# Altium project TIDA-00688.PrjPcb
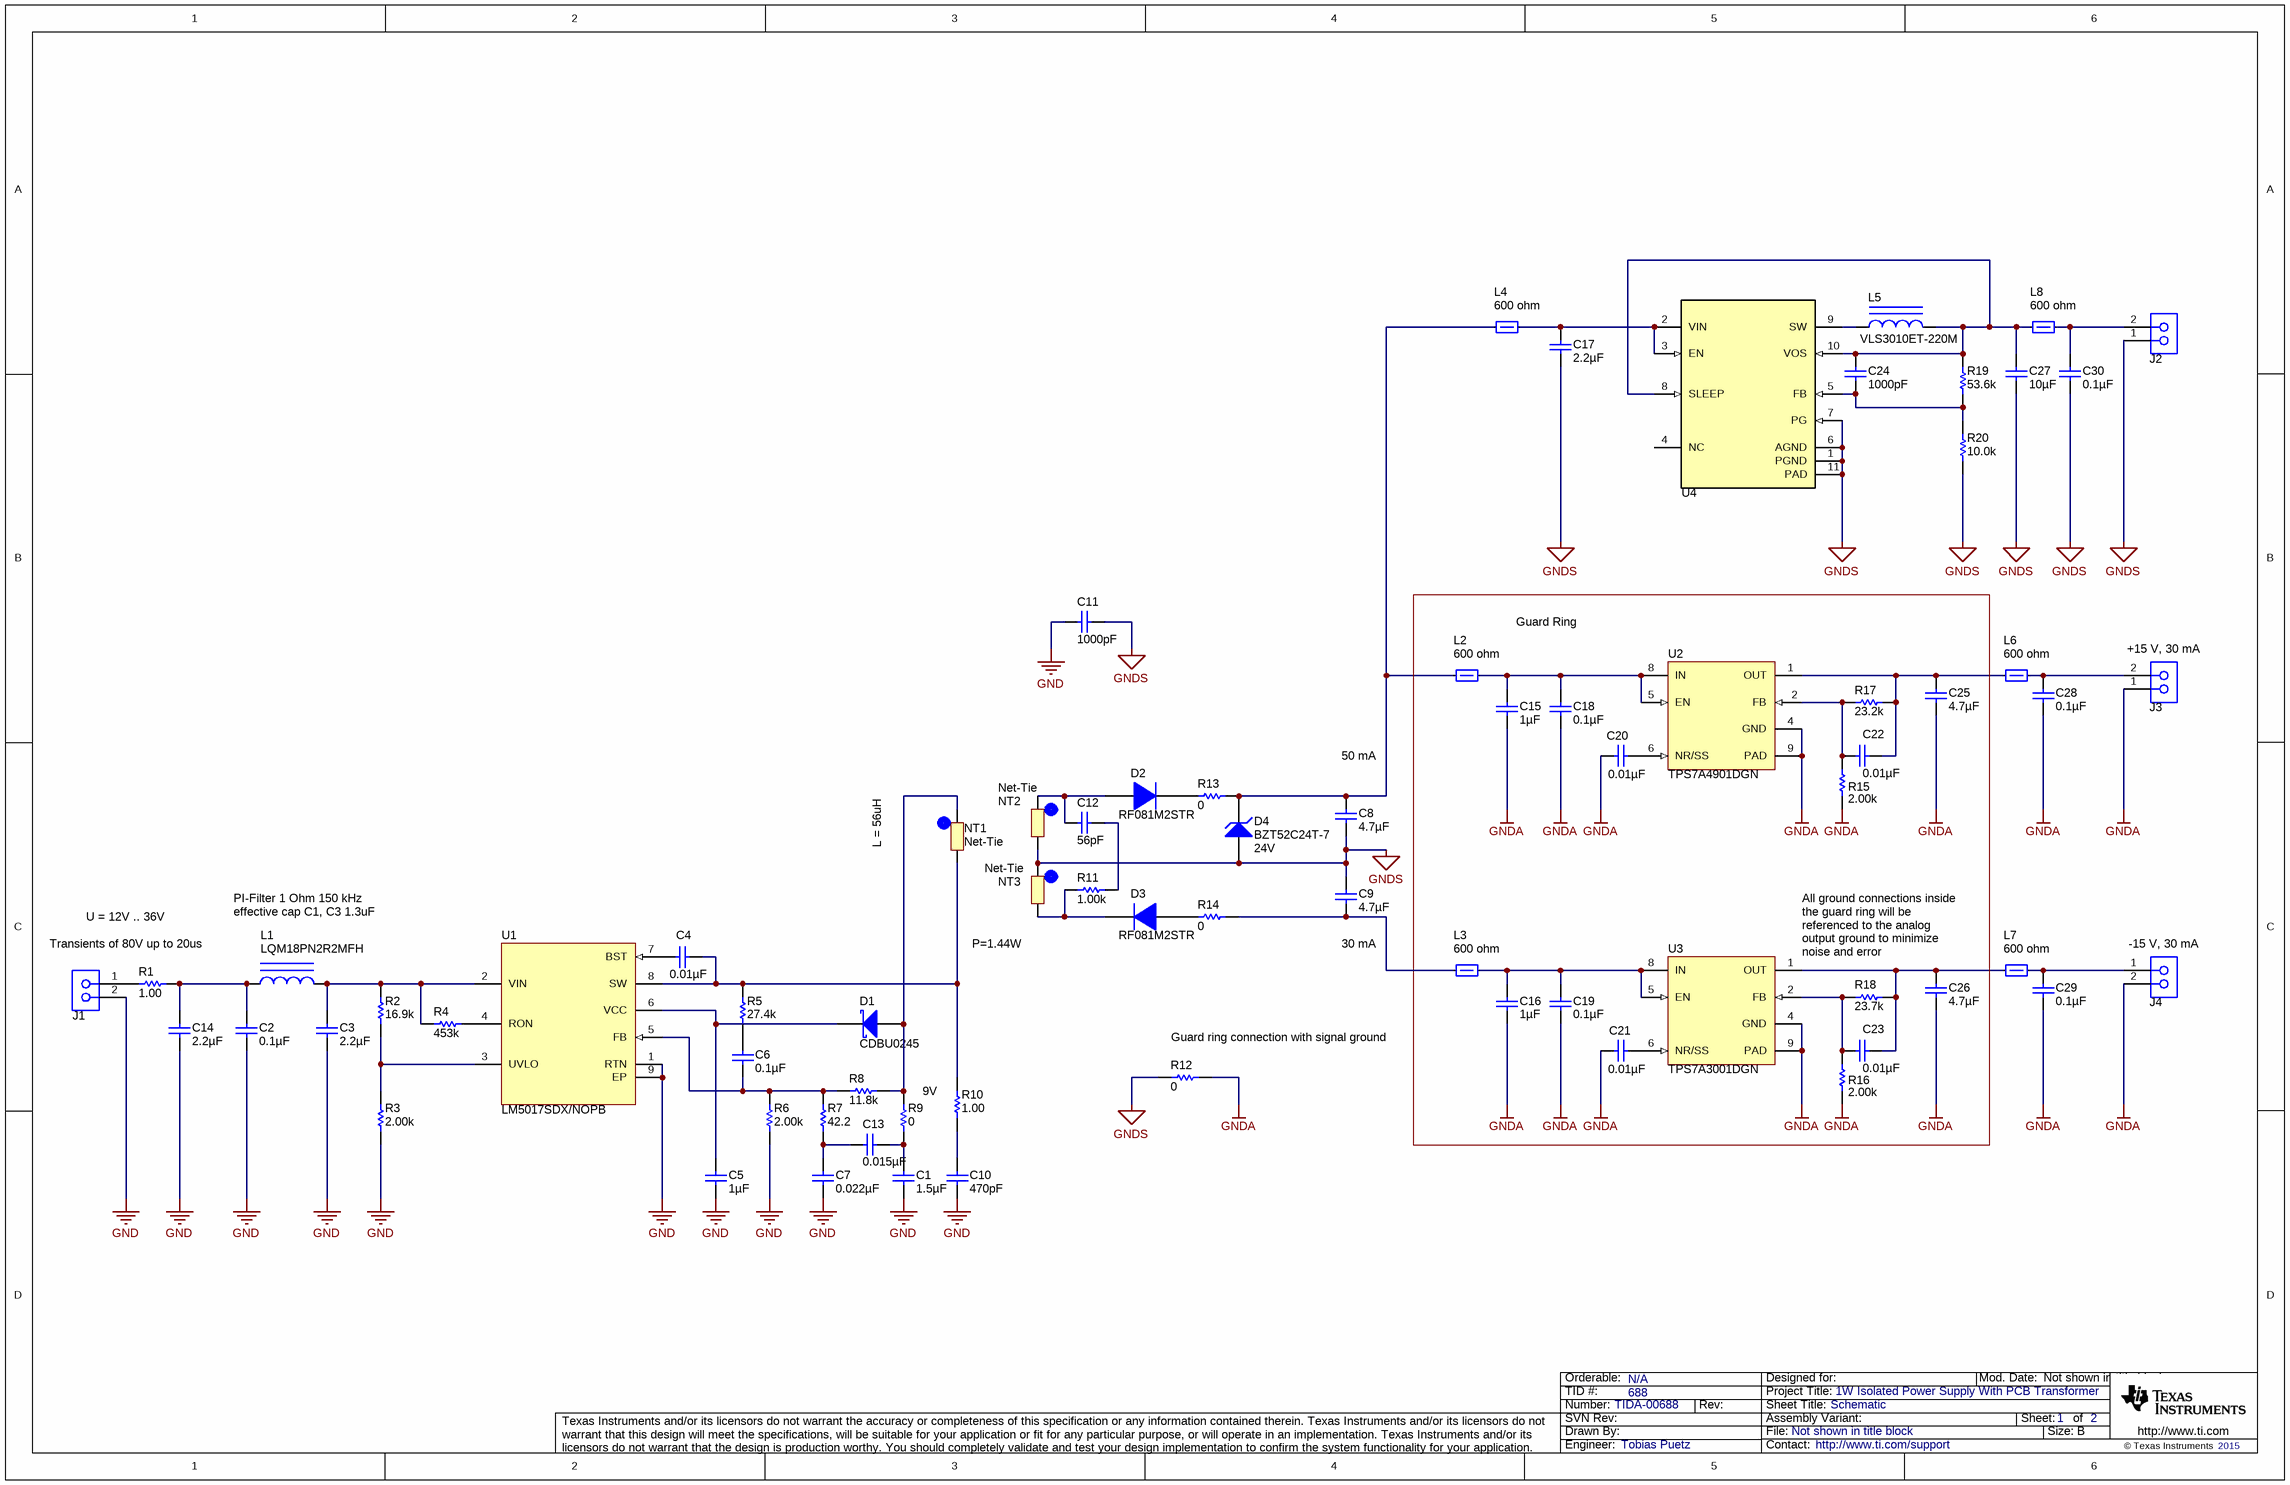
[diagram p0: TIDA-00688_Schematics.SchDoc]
CopyrightYear: 2015; EVM_Orderable: N/A; PCB_Layout: a0406826; PRJ_Engineer: Tobias Puetz; PRJ_Number: TIDA-00688; PRJ_Title: 1W Isolated Power Supply With PCB Transformer; TechSupport: http://www.ti.com/support; TID: 688
2 sheets, 83 parts. Net scope: global (net labels, ports and power ports of the same name join across sheets).
Board file: TIDA-00688.PcbDoc
Sheets:
  TIDA-00688_Schematics.SchDoc
  TIDA-00688_Hardware.SchDoc

## Sheet TIDA-00688_Schematics.SchDoc: Schematic
size 431 x 279 mm; Date: Not shown in title block; ApprovedBy: Not shown in title block; CheckedBy: Not shown in title block; Author: Not shown in title block; CompanyName: Not shown in title block; Engineer: Not shown in title block; Organization: Not shown in title block; Address1: Not shown in title block; Address2: Not shown in title block; Address3: Not shown in title block; Address4: Not shown in title block; DocumentNumber: 1; Revision: Use project parameter SCH_Rev; SheetNumber: 1; SheetTotal: 2; PageSetup: Record=PageOptions¦CenterHorizontal=True¦CenterVertical=True¦PrintScale=0.64¦XCorrection=1.00¦YCorrection=1.00¦PrintKind=0¦BorderSize=5000000¦LeftOffset=0¦BottomOffset=0¦Orientation=2¦PaperLength=1000¦PaperWidth=1000¦Scale=100¦PaperSource=15¦PrintQuality=600¦MediaType=1¦DitherType=10¦PrintScaleMode=1¦PaperKind=Letter

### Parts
C1  ValueDisplayed: 1.5µF  [0805_HV]  (hidden comment: GRM21BR71E155KA88L)
C2  ValueDisplayed: 0.1µF  [0603]  (hidden comment: C1608X7R1H104K)
C3  ValueDisplayed: 2.2µF  [1206_033]  (hidden comment: UMK316B7225KD-T)
C4  ValueDisplayed: 0.01µF  [0603]  (hidden comment: C0603C103J5RACTU)
C5  ValueDisplayed: 1µF  [0603]  (hidden comment: GRM188R71E105KA12D)
C6  ValueDisplayed: 0.1µF  [0603]  (hidden comment: GCM188R71H104KA57D)
C7  ValueDisplayed: 0.022µF  [0603]  (hidden comment: GRM188R71H223KA01D)
C8  ValueDisplayed: 4.7µF  [1206]  (hidden comment: GRM31CR71E475KA88L)
C9  ValueDisplayed: 4.7µF  [1206]  (hidden comment: GRM31CR71E475KA88L)
C10  ValueDisplayed: 470pF  [0603]  (hidden comment: C0603C471K5RACTU)
C11  ValueDisplayed: 1000pF  [1206_190]  (hidden comment: 202R18W102KV4E)
C12  ValueDisplayed: 56pF  [0805_HV]  (hidden comment: GRM21A5C2E560JW01D)
C13  ValueDisplayed: 0.015µF  [0603]  (hidden comment: GRM188R71H153KA01D)
C14  ValueDisplayed: 2.2µF  [1206_033]  (hidden comment: UMK316B7225KD-T)
C15  ValueDisplayed: 1µF  [0603]  (hidden comment: C0603C105K3RACTU)
C16  ValueDisplayed: 1µF  [0603]  (hidden comment: C0603C105K3RACTU)
C17  ValueDisplayed: 2.2µF  [0805_HV_033]  (hidden comment: C2012X7R1V225K085AC)
C18  ValueDisplayed: 0.1µF  [0603]  (hidden comment: C1608X7R1H104K)
C19  ValueDisplayed: 0.1µF  [0603]  (hidden comment: C1608X7R1H104K)
C20  ValueDisplayed: 0.01µF  [0603]  (hidden comment: C0603C103J5RACTU)
C21  ValueDisplayed: 0.01µF  [0603]  (hidden comment: C0603C103J5RACTU)
C22  ValueDisplayed: 0.01µF  [0603]  (hidden comment: C0603C103J5RACTU)
C23  ValueDisplayed: 0.01µF  [0603]  (hidden comment: C0603C103J5RACTU)
C24  ValueDisplayed: 1000pF  [0603]  (hidden comment: GRM188R71E102KA01D)
C25  ValueDisplayed: 4.7µF  [1206_033]  (hidden comment: C3216X7R1E475K085AB)
C26  ValueDisplayed: 4.7µF  [1206_033]  (hidden comment: C3216X7R1E475K085AB)
C27  ValueDisplayed: 10µF  [1206_033]  (hidden comment: C3216X7R1A106M085AC)
C28  ValueDisplayed: 0.1µF  [0603]  (hidden comment: C1608X7R1H104K)
C29  ValueDisplayed: 0.1µF  [0603]  (hidden comment: C1608X7R1H104K)
C30  ValueDisplayed: 0.1µF  [0603]  (hidden comment: C1608X7R1H104K)
D1  CDBU0245  [SOD-523F]
D2  RF081M2STR  [SOD-123]
D3  RF081M2STR  [SOD-123]
D4  BZT52C24T-7  value 24V  [SOD-523]
J1  1751248  [CONN_1751248]  (value not drawn)
J2  1751248  [CONN_1751248]  (value not drawn)
J3  1751248  [CONN_1751248]  (value not drawn)
J4  1751248  [CONN_1751248]  (value not drawn)
L1  LQM18PN2R2MFH  [0603]
L2  value 600 ohm  [0603]  (hidden comment: BLM18KG601SN1D)
L3  value 600 ohm  [0603]  (hidden comment: BLM18KG601SN1D)
L4  value 600 ohm  [0603]  (hidden comment: BLM18KG601SN1D)
L5  VLS3010ET-220M  [VLS3010]
L6  value 600 ohm  [0603]  (hidden comment: BLM18KG601SN1D)
L7  value 600 ohm  [0603]  (hidden comment: BLM18KG601SN1D)
L8  value 600 ohm  [0603]  (hidden comment: BLM18KG601SN1D)
NT1  Net-Tie  [Net-Tie_20milWide_60milLong]  (net tie, no BOM)
NT2  Net-Tie  [Net-Tie_20milWide_60milLong]  (net tie, no BOM)
NT3  Net-Tie  [Net-Tie_20milWide_60milLong]  (net tie, no BOM)
R1  ValueDisplayed: 1.00  [0603]  (hidden comment: CRCW06031R00FKEA)
R2  ValueDisplayed: 16.9k  [0603]  (hidden comment: CRCW060316K9FKEA)
R3  ValueDisplayed: 2.00k  [0603]  (hidden comment: CRCW06032K00FKEA)
R4  ValueDisplayed: 453k  [0603]  (hidden comment: CRCW0603453KFKEA)
R5  ValueDisplayed: 27.4k  [0603]  (hidden comment: CRCW060327K4FKEA)
R6  ValueDisplayed: 2.00k  [0603]  (hidden comment: CRCW06032K00FKEA)
R7  ValueDisplayed: 42.2  [0603]  (hidden comment: CRCW060342R2FKEA)
R8  ValueDisplayed: 11.8k  [0603]  (hidden comment: CRCW060311K8FKEA)
R9  ValueDisplayed: 0  [0603]  (hidden comment: ERJ-3GEY0R00V)
R10  ValueDisplayed: 1.00  [0603]  (hidden comment: CRCW06031R00FKEA)
R11  ValueDisplayed: 1.00k  [0805_HV]  (hidden comment: CRCW08051K00FKEA)
R12  ValueDisplayed: 0  [0603]  (hidden comment: CRCW06030000Z0EA)
R13  ValueDisplayed: 0  [0603]  (hidden comment: ERJ-3GEY0R00V)
R14  ValueDisplayed: 0  [0603]  (hidden comment: ERJ-3GEY0R00V)
R15  ValueDisplayed: 2.00k  [0603]  (hidden comment: CRCW06032K00FKEA)
R16  ValueDisplayed: 2.00k  [0603]  (hidden comment: CRCW06032K00FKEA)
R17  ValueDisplayed: 23.2k  [0603]  (hidden comment: CRCW060323K2FKEA)
R18  ValueDisplayed: 23.7k  [0603]  (hidden comment: CRCW060323K7FKEA)
R19  ValueDisplayed: 53.6k  [0603]  (hidden comment: CRCW060353K6FKEA)
R20  ValueDisplayed: 10.0k  [0603]  (hidden comment: CRCW060310K0FKEA)
U1  LM5017SDX/NOPB  [NGU0008B]
U2  TPS7A4901DGN  [DGN0008D_N]
U3  TPS7A3001DGN  [DGN0008D_N]
U4  TPS62175DQCR  [DQC0010A]  (value not drawn)

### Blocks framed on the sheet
Guard Ring: C15 C16 C18-C23 C25 C26 L2 L3 R15-R18 U2 U3

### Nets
GND: C1.2 C2.2 C3.2 C5.2 C7.2 C10.2 C11.2 C14.2 J1.2 R3.1 R6.1 U1.1(RTN) U1.9(EP)
GNDA: C15.2 C16.2 C18.2 C19.2 C20.1 C21.1 C25.2 C26.2 C28.2 C29.2 J3.1 J4.2 R12.2 R15.1 R16.1 U2.4(GND) U2.9(PAD) U3.4(GND) U3.9(PAD)
GNDS: C8.2 C9.1 C11.1 C17.2 C27.2 C30.2 D4.2(A) J2.1 NT2.1 NT3.1 R12.1 R20.1 U4.1(PGND) U4.6(AGND) U4.7(PG) U4.11(PAD)
NetC1_1: C1.1 C13.1 R9.1
NetC2_1: C2.1 C14.1 L1.1 R1.1
NetC3_1: C3.1 L1.2 R2.2 R4.1 U1.2(VIN)
NetC4_1: C4.1 U1.7(BST)
NetC4_2: C4.2 NT1.1 R5.1 R10.2 U1.8(SW)
NetC5_1: C5.1 D1.1(K) U1.6(VCC)
NetC6_1: C6.1 R5.2
NetC6_2: C6.2 R6.2 R7.2 R8.1 U1.5(FB)
NetC7_1: C7.1 C13.2 R7.1
NetC8_1: C8.1 D4.1(K) L2.1 L4.1 R13.1
NetC9_2: C9.2 L3.1 R14.1
NetC10_1: C10.1 R10.1
NetC12_1: C12.1 R11.1
NetC12_2: C12.2 D2.2(A) NT2.2
NetC15_1: C15.1 C18.1 L2.2 U2.5(EN) U2.8(IN)
NetC16_1: C16.1 C19.1 L3.2 U3.5(EN) U3.8(IN)
NetC17_1: C17.1 L4.2 U4.2(VIN) U4.3(EN)
NetC20_2: C20.2 U2.6(NR/SS)
NetC21_2: C21.2 U3.6(NR/SS)
NetC22_1: C22.1 R15.2 R17.1 U2.2(FB)
NetC22_2: C22.2 C25.1 L6.1 R17.2 U2.1(OUT)
NetC23_1: C23.1 R16.2 R18.1 U3.2(FB)
NetC23_2: C23.2 C26.1 L7.1 R18.2 U3.1(OUT)
NetC24_1: C24.1 C27.1 L5.2 L8.1 R19.2 U4.8(SLEEP) U4.10(VOS)
NetC24_2: C24.2 R19.1 R20.2 U4.5(FB)
NetC28_1: C28.1 J3.2 L6.2
NetC29_1: C29.1 J4.1 L7.2
NetC30_1: C30.1 J2.2 L8.2
NetD1_2: D1.2(A) NT1.2 R8.2 R9.2
NetD2_1: D2.1(K) R13.2
NetD3_1: D3.1(K) NT3.2 R11.2
NetD3_2: D3.2(A) R14.2
NetJ1_1: J1.1 R1.2
NetL5_1: L5.1 U4.9(SW)
NetR2_1: R2.1 R3.2 U1.3(UVLO)
NetR4_2: R4.2 U1.4(RON)

Not connected (* = marked no-connect by the designer): U2 3(NC) 7(DNC); U3 3(NC) 7(DNC); U4 4(NC)

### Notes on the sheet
- (near J3) +15 V, 30 mA
- (near C8) 50 mA
- L = 56uH
- U = 12V .. 36V
- Transients of 80V up to 20us
- PI-Filter 1 Ohm 150 kHz
  effective cap C1, C3 1.3uF
- (near NT3) P=1.44W
- (near C9) 30 mA
- All ground connections inside the guard ring will be referenced to the analog output ground to minimize noise and error
- (near J4) -15 V, 30 mA
- (near R12) Guard ring connection with signal ground
- 9V

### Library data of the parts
C1 = GRM21BR71E155KA88L: CAP, CERM, 1.5 µF, 25 V, +/- 10%, X7R, 0805; Manufacturer: MuRata; Polarized: N; CompType: Capacitor; Value: 1.5uF; U/M: EA; Cap_F: 0.0000015; Tolerance_%: 10; Value1: Unknown; VDC_V: 25; Value2: 25V; TaMin_C: -55; TaMax_C: 125; Cap_Case: 0805
C2 C18 C19 C28-C30 = C1608X7R1H104K: CAP, CERM, 0.1 µF, 50 V, +/- 10%, X7R, 0603; Manufacturer: TDK; Polarized: N; CompType: Capacitor; Value: 0.1uF; U/M: EA; Cap_F: 0.0000001; Tolerance_%: 10; ESR_ohm: 0.017; Value1: 0.017 ohm; VDC_V: 50; Value2: 50V; TaMin_C: -55; TaMax_C: 125
C3 C14 = UMK316B7225KD-T: CAP, CERM, 2.2 µF, 50 V, +/- 10%, X7R, 1206; Manufacturer: Taiyo Yuden; Polarized: N; CompType: Capacitor; Value: 2.2uF; U/M: EA; Cap_F: 0.0000022; Tolerance_%: 10; Value1: Unknown; VDC_V: 50; Value2: 50V; TaMin_C: -55; TaMax_C: 125; Cap_Case: 1206
C4 C20-C23 = C0603C103J5RACTU: CAP, CERM, 0.01 µF, 50 V, +/- 5%, X7R, 0603; Manufacturer: Kemet; Polarized: N; CompType: Capacitor; Value: 0.01uF; U/M: EA; Cap_F: 0.00000001; Tolerance_%: 5; Value1: Unknown; VDC_V: 50; Value2: 50V; TaMin_C: -55; TaMax_C: 125
C5 = GRM188R71E105KA12D: CAP, CERM, 1 µF, 25 V, +/- 10%, X7R, 0603; Manufacturer: MuRata; Polarized: N; CompType: Capacitor; Value: 1uF; U/M: EA; Cap_F: 0.000001; Tolerance_%: 10; Value1: Unknown; VDC_V: 25; Value2: 25V; TaMin_C: -55; TaMax_C: 125
C6 = GCM188R71H104KA57D: CAP, CERM, 0.1 µF, 50 V, +/- 10%, X7R, 0603; Manufacturer: MuRata; Polarized: N; CompType: Capacitor; Value: 0.1uF; U/M: EA; Cap_F: 0.0000001; Tolerance_%: 10; ESR_ohm: 0.02; Value1: 0.02 ohm; VDC_V: 50; Value2: 50V; IRMS_A: 1.84; TaMin_C: -55; TaMax_C: 125
C7 = GRM188R71H223KA01D: CAP, CERM, 0.022 µF, 50 V, +/- 10%, X7R, 0603; Manufacturer: MuRata; Polarized: N; CompType: Capacitor; Value: 0.022uF; U/M: EA; Cap_F: 0.000000022; Tolerance_%: 10; Value1: Unknown; VDC_V: 50; Value2: 50V; TaMin_C: -55; TaMax_C: 125; AEC Category: Q200
C8 C9 = GRM31CR71E475KA88L: CAP, CERM, 4.7 µF, 25 V, +/- 10%, X7R, 1206; Manufacturer: MuRata; Polarized: N; CompType: Capacitor; Value: 4.7uF; U/M: EA; Cap_F: 0.0000047; Tolerance_%: 10; Value1: Unknown; VDC_V: 25; Value2: 25V; TaMin_C: -55; TaMax_C: 125
C10 = C0603C471K5RACTU: CAP, CERM, 470 pF, 50 V, +/- 10%, X7R, 0603; Manufacturer: Kemet; Polarized: N; CompType: Capacitor; Value: 470pF; U/M: EA; Cap_F: 0.00000000047; Tolerance_%: 10; Value1: Unknown; VDC_V: 50; Value2: 50V; TaMin_C: -55; TaMax_C: 125
C11 = 202R18W102KV4E: CAP, CERM, 1000 pF, 2000 V, +/- 10%, X7R, 1206_190; Manufacturer: Johanson Technology; Polarized: N; CompType: Capacitor; Value: 1000pF; U/M: EA; Cap_F: 0.000000001; Tolerance_%: 10; Value1: Unknown; VDC_V: 2000; Value2: 2000V; TaMin_C: -55; TaMax_C: 125; Cap_Case: 1206
C12 = GRM21A5C2E560JW01D: CAP, CERM, 56 pF, 250 V, +/- 5%, C0G/NP0, 0805; Manufacturer: MuRata; Polarized: N; CompType: Capacitor; Value: 56pF; U/M: EA; Cap_F: 0.000000000056; Tolerance_%: 5; Value1: Unknown; VDC_V: 250; Value2: 250V; TaMin_C: -55; TaMax_C: 125; Cap_Case: 0805
C13 = GRM188R71H153KA01D: CAP, CERM, 0.015 µF, 50 V, +/- 10%, X7R, 0603; Manufacturer: MuRata; Polarized: N; CompType: Capacitor; Value: 0.015uF; U/M: EA; Cap_F: 0.000000015; Tolerance_%: 10; Value1: Unknown; VDC_V: 50; Value2: 50V; TaMin_C: -55; TaMax_C: 125; AEC Category: Q200
C15 C16 = C0603C105K3RACTU: CAP, CERM, 1 µF, 25 V, +/- 10%, X7R, 0603; Manufacturer: Kemet; Polarized: N; CompType: Capacitor; Value: 1uF; U/M: EA; Cap_F: 0.000001; Tolerance_%: 10; Value1: Unknown; VDC_V: 25; Value2: 25V; TaMin_C: -55; TaMax_C: 125; AEC Category: Q200
C17 = C2012X7R1V225K085AC: CAP, CERM, 2.2 µF, 35 V, +/- 10%, X7R, 0805; Manufacturer: TDK; Polarized: N; CompType: Capacitor; Value: 2.2uF; U/M: EA; Cap_F: 0.0000022; Tolerance_%: 10; Value1: Unknown; VDC_V: 35; Value2: 35V; TaMin_C: -55; TaMax_C: 125; Cap_Case: 0805
C24 = GRM188R71E102KA01D: CAP, CERM, 1000 pF, 25 V, +/- 10%, X7R, 0603; Manufacturer: MuRata; Polarized: N; CompType: Capacitor; Value: 1000pF; U/M: EA; Cap_F: 0.000000001; Tolerance_%: 10; Value1: Unknown; VDC_V: 25; Value2: 25V; TaMin_C: -55; TaMax_C: 125
C25 C26 = C3216X7R1E475K085AB: CAP, CERM, 4.7 µF, 25 V, +/- 10%, X7R, 1206; Manufacturer: TDK; Polarized: N; CompType: Capacitor; Value: 4.7uF; U/M: EA; Cap_F: 0.0000047; Tolerance_%: 10; ESR_ohm: 0.0063; Value1: 0.0063 ohm; VDC_V: 25; Value2: 25V; TaMin_C: -55; TaMax_C: 125; Cap_Case: 1206
C27 = C3216X7R1A106M085AC: CAP, CERM, 10 µF, 10 V, +/- 20%, X7R, 1206; Manufacturer: TDK; Polarized: N; CompType: Capacitor; Value: 10uF; U/M: EA; Cap_F: 0.00001; Tolerance_%: 20; ESR_ohm: 0.0046; Value1: 0.0046 ohm; VDC_V: 10; Value2: 10V; TaMin_C: -55; TaMax_C: 125; Cap_Case: 1206
D1 = CDBU0245: Diode, Schottky, 45 V, 0.2 A, SOD-523F; Manufacturer: Comchip Technology; Value: 45V; U/M: EA; Value1: 0.2A; Io_A: 0.2; Vr_V: 45; TJmax_C: 125
D2 D3 = RF081M2STR: Diode, Fast Rectifier, 200 V, 0.8 A, SOD-123; Manufacturer: Rohm; Value: 200V; U/M: EA; Vf_V: 0.95; Value1: 0.8A; Value2: 0.95V; Io_A: 0.8; Vr_V: 200; TJmax_C: 150
D4 = BZT52C24T-7: Diode, Zener, 24 V, 300 mW, SOD-523; Manufacturer: Diodes Inc.; SymbolCreator: a0412235; U/M: EA; Power_W: 0.3; Vz_V: 24; Value1: 0.3W; RJA_CperW: 417
J1-J4 = 1751248: Conn Term Block, 2POS, 3.5mm, TH; Manufacturer: Phoenix Contact; Alternate Manufacturer: Any; Alternate PartNumber: Equivalent; Value: 2x1; CompType: Terminal Block; U/M: EA
L1 = LQM18PN2R2MFH: Inductor, Ferrite, 2.2 µH, 0.35 A, 0.38 ohm, SMD; Manufacturer: MuRata; Value: 2.2uH; Imax_A: 0.35; DCR_ohm: 0.38; Value2: 0.35A; Ind_H: 2.2E-6; ValueDisplayed: 2.2µH; Irms: 0.9A @ 40C rise; Isat: 0.35A @ 30% inductance drop
L2-L4 L6-L8 = BLM18KG601SN1D: Ferrite Bead, 600 ohm @ 100 MHz, 1.3 A, 0603; Manufacturer: MuRata; Imax_A: 1.3; DCR_ohm: 0.15; Value1: 0.15 ohm; Value2: 1.3A; ZTyp@100MHz_Ohm: 600
L5 = VLS3010ET-220M: Inductor, Shielded, Ferrite, 22 µH, 0.38 A, 0.9 ohm, SMD; Manufacturer: TDK; Value: 22uH; Ind_H: 22.0E-6; ValueDisplayed: 22µH; Imax_A: 0.38; Irms: 0.6A @ 40C rise; Isat: 0.38A @ 30% inductance drop; DCR_ohm: 0.9; Value1: 0.9 ohm; Value2: 0.38A
NT1-NT3 = Net-Tie: Single point connection between nets.; SymbolCreator: codlsc
R1 R10 = CRCW06031R00FKEA: RES, 1.00, 1%, 0.1 W, 0603; Manufacturer: Vishay-Dale; CompType: Resistor; Value: 1.00; Res_ohm: 1; Value_Code: 1R00; Power_W: 0.1; Value2: 0.1W; VDC_V: 75; TempCo: 100 ppm/C; EIA_Code: E96; U/M: EA
R2 = CRCW060316K9FKEA: RES, 16.9 k, 1%, 0.1 W, 0603; Manufacturer: Vishay-Dale; CompType: Resistor; Value: 16.9k; Res_ohm: 16900; Value_Code: 16k9; Tolerance_%: 1; Power_W: 0.1; Value2: 0.1W; VDC_V: 75; TempCo: 100 ppm/C; EIA_Code: E96; U/M: EA
R3 R6 R15 R16 = CRCW06032K00FKEA: RES, 2.00 k, 1%, 0.1 W, 0603; Manufacturer: Vishay-Dale; CompType: Resistor; Value: 2.00k; Res_ohm: 2000; Value_Code: 2k00; Tolerance_%: 1; Power_W: 0.1; Value2: 0.1W; VDC_V: 75; TempCo: 100 ppm/C; EIA_Code: E96; U/M: EA
R4 = CRCW0603453KFKEA: RES, 453 k, 1%, 0.1 W, 0603; Manufacturer: Vishay-Dale; CompType: Resistor; Value: 453k; Res_ohm: 453000; Tolerance_%: 1; Power_W: 0.1; Value2: 0.1W; VDC_V: 75; TempCo: 100 ppm/C; EIA_Code: E96; U/M: EA
R5 = CRCW060327K4FKEA: RES, 27.4 k, 1%, 0.1 W, 0603; Manufacturer: Vishay-Dale; CompType: Resistor; Value: 27.4k; Res_ohm: 27400; Value_Code: 27k4; Tolerance_%: 1; Power_W: 0.1; Value2: 0.1W; VDC_V: 75; TempCo: 100 ppm/C; EIA_Code: E96; U/M: EA
R7 = CRCW060342R2FKEA: RES, 42.2, 1%, 0.1 W, 0603; Manufacturer: Vishay-Dale; CompType: Resistor; Value: 42.2; Value_Code: 42R2; Tolerance_%: 1; Power_W: 0.1; Value2: 0.1W; VDC_V: 75; TempCo: 100 ppm/C; EIA_Code: E96; U/M: EA
R8 = CRCW060311K8FKEA: RES, 11.8 k, 1%, 0.1 W, 0603; Manufacturer: Vishay-Dale; CompType: Resistor; Value: 11.8k; Res_ohm: 11800; Value_Code: 11k8; Tolerance_%: 1; Power_W: 0.1; Value2: 0.1W; VDC_V: 75; TempCo: 100 ppm/C; EIA_Code: E96; U/M: EA
R9 R13 R14 = ERJ-3GEY0R00V: RES, 0, 5%, 0.1 W, 0603; Manufacturer: Panasonic; CompType: Resistor; Value: 0; Value_Code: 0000; Tolerance_%: 5; Power_W: 0.1; Value2: 0.1W; VDC_V: 50; TempCo: 600 ppm/C; EIA_Code: E24; U/M: EA
R11 = CRCW08051K00FKEA: RES, 1.00 k, 1%, 0.125 W, 0805; Manufacturer: Vishay-Dale; CompType: Resistor; Value: 1.00k; Res_ohm: 1000; Value_Code: 1k00; Tolerance_%: 1; Power_W: 0.125; Value2: 0.125W; VDC_V: 150; TempCo: 100 ppm/C; EIA_Code: E96; U/M: EA
R12 = CRCW06030000Z0EA: RES, 0, 5%, 0.1 W, 0603; Manufacturer: Vishay-Dale; CompType: Resistor; Value: 0; Value_Code: 0000; Tolerance_%: 5; Power_W: 0.1; Value2: 0.1W; VDC_V: 75; TempCo: 200 ppm/C; EIA_Code: E24; U/M: EA
R17 = CRCW060323K2FKEA: RES, 23.2 k, 1%, 0.1 W, 0603; Manufacturer: Vishay-Dale; CompType: Resistor; Value: 23.2k; Res_ohm: 23200; Value_Code: 23k2; Tolerance_%: 1; Power_W: 0.1; Value2: 0.1W; VDC_V: 75; TempCo: 100 ppm/C; EIA_Code: E96; U/M: EA
R18 = CRCW060323K7FKEA: RES, 23.7 k, 1%, 0.1 W, 0603; Manufacturer: Vishay-Dale; CompType: Resistor; Value: 23.7k; Res_ohm: 23700; Value_Code: 23k7; Tolerance_%: 1; Power_W: 0.1; Value2: 0.1W; VDC_V: 75; TempCo: 100 ppm/C; EIA_Code: E96; U/M: EA; AEC Category: Q200
R19 = CRCW060353K6FKEA: RES, 53.6 k, 1%, 0.1 W, 0603; Manufacturer: Vishay-Dale; CompType: Resistor; Value: 53.6k; Res_ohm: 53600; Value_Code: 53k6; Tolerance_%: 1; Power_W: 0.1; Value2: 0.1W; VDC_V: 75; TempCo: 100 ppm/C; EIA_Code: E96; U/M: EA
R20 = CRCW060310K0FKEA: RES, 10.0 k, 1%, 0.1 W, 0603; Manufacturer: Vishay-Dale; CompType: Resistor; Value: 10.0k; Res_ohm: 10000; Value_Code: 10k0; Tolerance_%: 1; Power_W: 0.1; Value2: 0.1W; VDC_V: 75; TempCo: 100 ppm/C; EIA_Code: E96; U/M: EA
U1 = LM5017SDX/NOPB: 100V, 600mA Constant On-Time Synchronous Buck Regulator, NGU0008B; Alternate PartNumber: LM5017SD/NOPB; Manufacturer: Texas Instruments; SymbolCreator: a0412235; CompType: IC; U/M: EA
U2 = TPS7A4901DGN: +36V, +150mA, Ultralow-Noise, Positive LINEAR REGULATOR, DGN0008D; Manufacturer: Texas Instruments; SymbolCreator: a0411947; CompType: IC; U/M: EA
U3 = TPS7A3001DGN: -36V, -200mA, Ultralow-Noise, High PSRR, Adjustable -1.18 to -33 V Output, Negative Linear Regulator, 8-pin MSOP (DGN), -40 to 125 degC, Green (RoHS & no Sb/Br); Manufacturer: Texas Instruments; Alternate Manufacturer: None; Alternate PartNumber: Equivalent; Accuracy(%): 1.5; Iout(Max)(A): 0.2; Iq(Typ)(mA): 0.05; SubFamily: Single Channel LDO; Vdo(Typ)(mV): 216; Vin(Max)(V): -36; Vin(Min)(V): -3
U4 = TPS62175DQCR: 28V, 0.5A Step-Down Converter with Sleep Mode, DQC0010A; Alternate PartNumber: TPS62175DQCT; Manufacturer: Texas Instruments; SymbolCreator: a0411947; CompType: IC; U/M: EA

## Sheet TIDA-00688_Hardware.SchDoc: Hardware
size 431 x 279 mm; Date: Not shown in title block; ApprovedBy: Not shown in title block; CheckedBy: Not shown in title block; Author: Not shown in title block; CompanyName: Not shown in title block; Engineer: Not shown in title block; Organization: Not shown in title block; Address1: Not shown in title block; Address2: Not shown in title block; Address3: Not shown in title block; Address4: Not shown in title block; DocumentNumber: 2; Revision: Use project parameter SCH_Rev; SheetNumber: 2; SheetTotal: 2; PageSetup: Record=PageOptions¦CenterHorizontal=True¦CenterVertical=True¦PrintScale=1.00¦XCorrection=1.00¦YCorrection=1.00¦PrintKind=0¦BorderSize=5000000¦LeftOffset=0¦BottomOffset=0¦Orientation=2¦PaperLength=1000¦PaperWidth=1000¦Scale=100¦PaperSource=15¦PrintQuality=600¦MediaType=1¦DitherType=10¦PaperKind=Letter¦PrintScaleMode=1
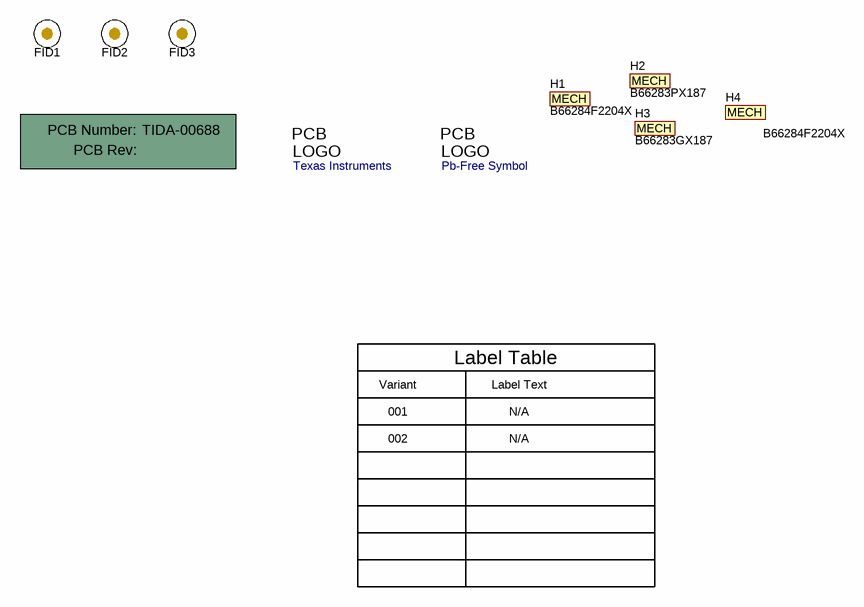
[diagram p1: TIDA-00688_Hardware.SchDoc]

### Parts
!PCB  Printed Circuit Board  (value not drawn)  (mechanical)
FID1  Fiducial  [Fiducial10-20]  (value not drawn)
FID2  Fiducial  [Fiducial10-20]  (value not drawn)
FID3  Fiducial  [Fiducial10-20]  (value not drawn)
H1  B66284F2204X  (mechanical)
H2  B66283PX187  (mechanical)
H3  B66283GX187  (mechanical)
H4  B66284F2204X  (mechanical)
Logo1  Texas Instruments  [TI_Symbol_Overlay_Small]  (no BOM)
Logo2  Pb-Free Symbol  [Pb-Free_Overlay_Small]  (no BOM)

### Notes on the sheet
- Variant
- Label Table
- Label Text
- 001
- 002
- N/A

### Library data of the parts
!PCB = PCB: Manufacturer: Any; PartNumber: TIDA-00688; SymbolCreator: a0412235
FID1-FID3 = Fiducial: Fiducial mark.  There is nothing to buy or mount.; SymbolCreator: codlsc
H1 H4 = B66284F2204X: CLAMP ELP 18X4X10 I 18X2X10; Manufacturer: TDK; SymbolCreator: codlsc
H2 = B66283PX187: FERRITE CORE ELP 2.9UH N87; Manufacturer: TDK; SymbolCreator: codlsc
H3 = B66283GX187: Ferrite Core, ELP, 2.6uH, N87; Manufacturer: TDK; SymbolCreator: codlsc
Logo1 = TI_Logo: Texas Instrument Corporate Signature; SymbolCreator: a0412235
Logo2 = Pb-Free: SymbolCreator: a0412235

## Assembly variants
Final TIDA-00688: not fitted C12 C13 R11
TIDA-00688: all parts fitted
